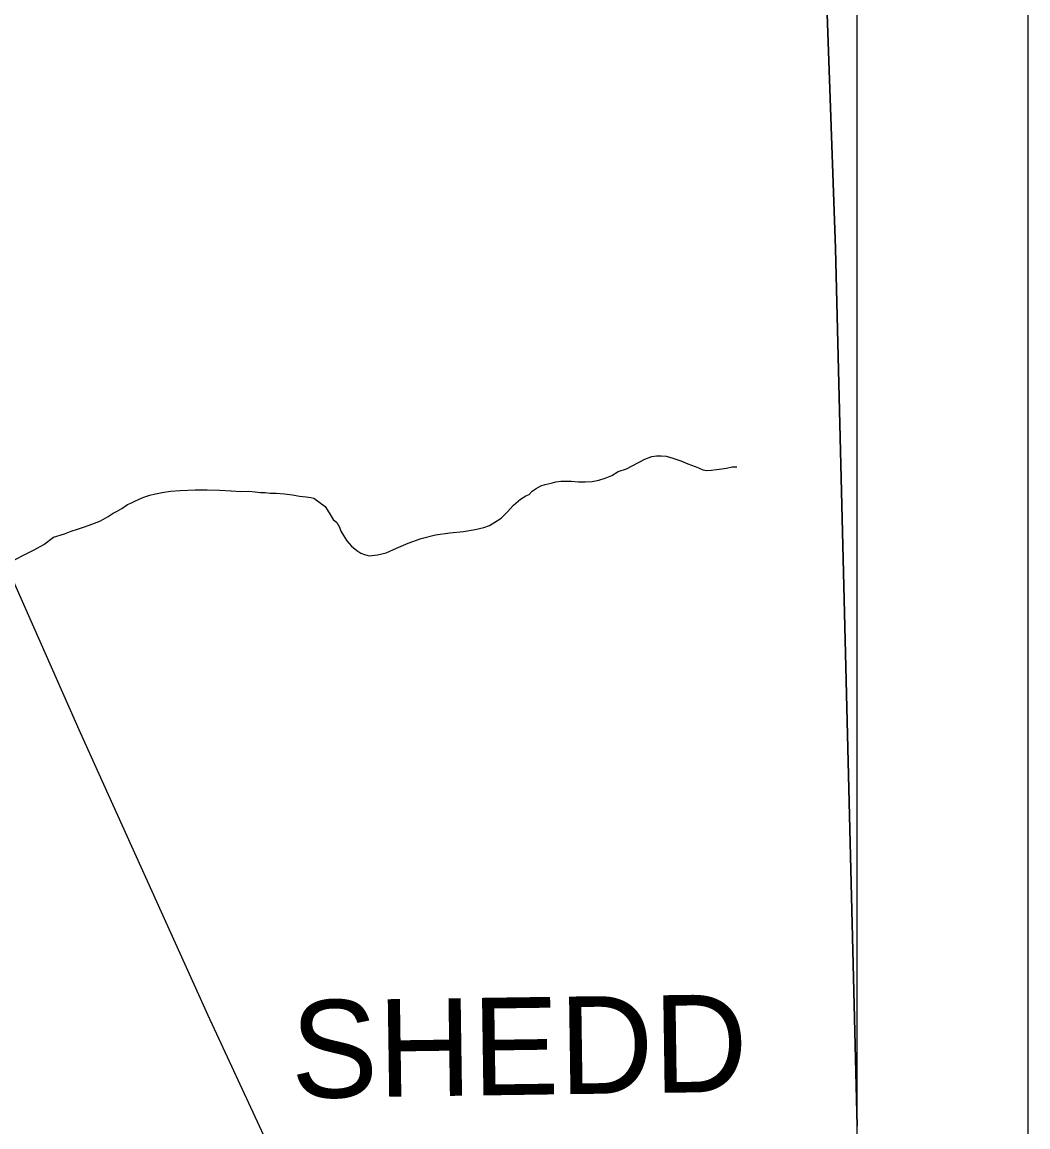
# Model space of a CAD drawing. Extents: x 0 to 34, y 0 to 22.
# Drawn here: x 8.676 to 9.262, y 19.769 to 20.413 of the extents above; entities that cross this region are included whole.
import ezdxf

# ---------------------------------------------------------------- set-up
doc = ezdxf.new("R2010")
doc.units = 0
for name, color, linetype in [('GM_X_County', 7, 'Continuous'), ('GM_X_Minor_River', 7, 'Continuous'), ('GM_X_State_Route', 7, 'Continuous'), ('GM_X_Township', 7, 'Continuous'), ('GM_X_Township_Road_Text', 7, 'Continuous'), ('SH_Data', 7, 'Continuous')]:
    doc.layers.add(name, color=color, linetype=linetype)

msp = doc.modelspace()

# ---------------------------------------------------------------- linework, layer by layer
at = {"layer": 'GM_X_County'}
msp.add_lwpolyline([(9.16225, 14.34203), (9.16225, 21.13849), (2.36225, 21.13849), (2.36225, 14.33849), (9.00028, 14.33849)], dxfattribs=at)
at = {"layer": 'GM_X_Minor_River'}
for points in [[(8.96944, 20.13695), (8.97133, 20.13773), (8.97321, 20.13964), (8.97548, 20.14117), (8.97812, 20.14271), (8.98077, 20.14349), (8.98418, 20.14428), (8.98683, 20.14506), (8.98987, 20.14546), (8.99252, 20.14548), (8.99594, 20.1455), (9.00012, 20.14516), (9.00391, 20.14518), (9.00809, 20.14521), (9.01187, 20.146), (9.01566, 20.14717), (9.01944, 20.14872), (9.02322, 20.15102), (9.02814, 20.15258), (9.03872, 20.15835), (9.04289, 20.15991), (9.04554, 20.1603), (9.0482, 20.16032), (9.05124, 20.15997), (9.05504, 20.15885), (9.05961, 20.15737), (9.0638, 20.1555), (9.06798, 20.15401), (9.06988, 20.15326), (9.07255, 20.15214), (9.07483, 20.15178), (9.07749, 20.1518), (9.08052, 20.1522), (9.08355, 20.1526), (9.08621, 20.153), (9.08962, 20.15379), (9.09151, 20.1538), (9.09227, 20.15381)], [(8.67218, 20.09983), (8.67747, 20.10252), (8.68314, 20.1056), (8.68881, 20.10868), (8.69447, 20.1129), (8.70091, 20.11485), (8.70469, 20.1164), (8.70848, 20.11757), (8.71188, 20.11873), (8.71529, 20.11989), (8.71832, 20.12106), (8.72134, 20.12222), (8.72361, 20.12338), (8.72626, 20.12491), (8.72928, 20.12684), (8.73155, 20.12799), (8.73419, 20.12953), (8.73759, 20.13184), (8.73948, 20.13261), (8.74175, 20.13377), (8.7444, 20.13492), (8.74705, 20.13608), (8.75045, 20.13725), (8.75386, 20.13803), (8.75765, 20.13882), (8.76258, 20.13962), (8.76827, 20.14004), (8.77699, 20.14048), (8.78383, 20.14053), (8.79104, 20.14021), (8.79787, 20.13988), (8.80357, 20.13954), (8.80812, 20.13957), (8.81192, 20.13922), (8.81496, 20.13886), (8.81762, 20.13888), (8.82065, 20.13852), (8.82407, 20.13855), (8.82901, 20.1382), (8.83357, 20.13748), (8.83775, 20.13675), (8.84154, 20.1364), (8.8442, 20.13603), (8.8461, 20.13567), (8.85259, 20.13078), (8.8549, 20.127), (8.85721, 20.12321), (8.8595, 20.12133), (8.86104, 20.11868), (8.86181, 20.11641), (8.86335, 20.11376), (8.86527, 20.11074), (8.86795, 20.10772), (8.87101, 20.10508), (8.8733, 20.10358), (8.87558, 20.10283), (8.87824, 20.10209), (8.88317, 20.10251), (8.8881, 20.10369), (8.89415, 20.10639), (8.90096, 20.10948), (8.90853, 20.11219), (8.91686, 20.11415), (8.9252, 20.11535), (8.93316, 20.11617), (8.93999, 20.11736), (8.94491, 20.11854), (8.94832, 20.1197), (8.95134, 20.12162), (8.95512, 20.12393), (8.95851, 20.12737), (8.96227, 20.13158), (8.96642, 20.13503), (8.96944, 20.13695)]]:
    msp.add_lwpolyline(points, dxfattribs=at)
at = {"layer": 'GM_X_State_Route'}
msp.add_lwpolyline([(8.81685, 19.7645), (8.78453, 19.83431), (8.71016, 19.99894), (8.64236, 20.15192), (8.58579, 20.27904), (8.57096, 20.31231), (8.53049, 20.40257), (8.49829, 20.47354)], dxfattribs=at)
at = {"layer": 'GM_X_Township'}
msp.add_line((9.16225, 19.7691), (9.16225, 19.76988), dxfattribs=at)
for points in [[(9.16225, 19.76988), (9.1497, 20.28105), (9.14061, 20.53789), (9.13183, 21.05151), (9.12907, 21.13849)], [(9.16225, 19.76988), (9.16225, 21.13849), (9.12907, 21.13849)], [(9.12907, 21.13849), (9.13183, 21.05151), (9.14061, 20.53789), (9.1497, 20.28105), (9.16225, 19.76988)]]:
    msp.add_lwpolyline(points, dxfattribs=at)
at = {"layer": 'SH_Data'}
msp.add_line((9.26174, 21.23826), (9.26174, 14.23826), dxfattribs=at)

# ---------------------------------------------------------------- texts
at = {"layer": 'GM_X_Township_Road_Text'}
msp.add_text('SHEDD', height=0.056818, rotation=0.8252, dxfattribs=at).set_placement((8.83298, 19.78621))

doc.saveas('drawing.dxf')
